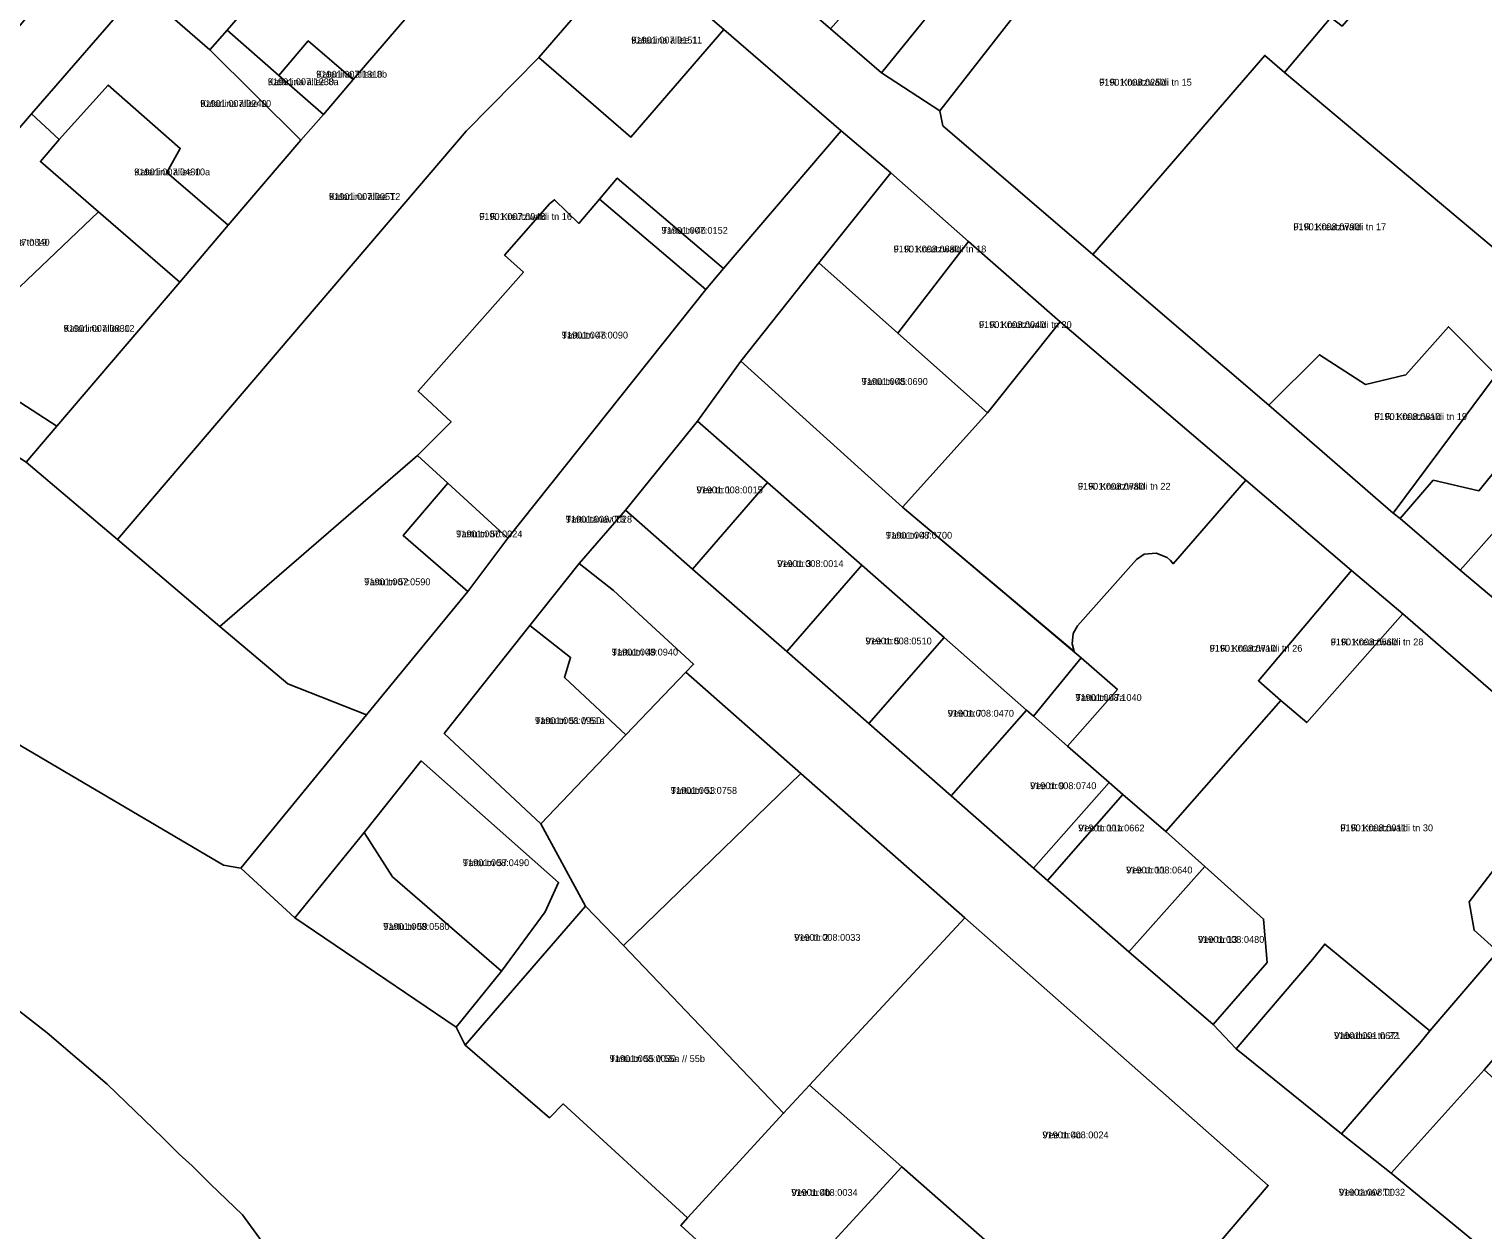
# Model space of a CAD drawing. Extents: x 675810 to 681273, y 6411190 to 6417565.
# Drawn here: x 677508.4 to 677826.5, y 6415288.2 to 6415551.1 of the extents above; entities that cross this region are included whole.
import ezdxf

# ---------------------------------------------------------------- set-up
doc = ezdxf.new("R2010")
doc.units = 0
for name, color, linetype in [('L_AADRESS', 7, 'Continuous'), ('PIIR', 7, 'Continuous'), ('TUNNUS', 7, 'Continuous')]:
    doc.layers.add(name, color=color, linetype=linetype)

msp = doc.modelspace()

# ---------------------------------------------------------------- linework, layer by layer
at = {"layer": 'PIIR'}
for points in [[(677842.69, 6415606.39), (677795.01, 6415644.29), (677786.34, 6415633.16), (677765.5, 6415606.74), (677740.8, 6415575.7), (677707.68, 6415533.22), (677694.9, 6415541.55), (677704.67, 6415553.58), (677711.53, 6415562.1), (677736.52, 6415593.55), (677779.85, 6415648.18), (677801.3, 6415675.96), (677820.17, 6415699.87), (677831.96, 6415720.82)], [(677495.67, 6415713.67), (677508.64, 6415702.82), (677531.61, 6415681.39), (677532.23, 6415682.05), (677579.84, 6415640.53), (677582.81, 6415640.69), (677592.98, 6415629.43), (677599.34, 6415623.94), (677607.64, 6415617.12), (677629.42, 6415597.96), (677651.47, 6415579), (677664.86, 6415567.49), (677683.76, 6415551.18), (677694.9, 6415541.55), (677707.68, 6415533.22), (677708.33, 6415529.95), (677741.16, 6415501.73), (677779.68, 6415468.8), (677806.89, 6415445.16), (677808.38, 6415444), (677821.56, 6415432.66), (677839.41, 6415417.62)], [(677841.37, 6415395.02), (677809, 6415423.1), (677797.76, 6415432.58), (677774.64, 6415452.34), (677734.01, 6415487.03), (677713.91, 6415504.57), (677696.92, 6415519.61), (677686.05, 6415528.82), (677660.36, 6415551.02), (677640.22, 6415568.39), (677619.3, 6415586.7), (677597.33, 6415605.55), (677583.03, 6415617.83), (677571.56, 6415627.5), (677552.93, 6415643.54), (677533.97, 6415659.49), (677514.58, 6415676.17), (677498.11, 6415690.24)], [(677747.14, 6415260.04), (677779.53, 6415298.01), (677713.15, 6415356.53), (677677.25, 6415388.18), (677652.1, 6415410.33), (677653.79, 6415412.07), (677636.22, 6415428.22), (677628.7, 6415434.13), (677638.86, 6415445.76), (677653.53, 6415432.91), (677674.17, 6415414.84), (677692.1, 6415399.1), (677710.14, 6415383.26), (677728.17, 6415367.42), (677731.22, 6415364.74), (677749.05, 6415349.09), (677767.49, 6415333.18), (677772.54, 6415327.91), (677795.57, 6415309.3), (677806.4, 6415300.64), (677832.58, 6415279.14)], [(677485.36, 6415406.68), (677550.88, 6415368.11), (677554.69, 6415367.45), (677566.49, 6415356.58), (677601.8, 6415332.63), (677603.77, 6415328.68), (677622.25, 6415312.81), (677625.2, 6415315.85), (677652.45, 6415290.88), (677650.98, 6415289.25), (677670.83, 6415271.06), (677666.68, 6415266.54), (677648.5, 6415245.63), (677700.59, 6415199.01), (677718.76, 6415219.92), (677731.04, 6415208.96), (677712.89, 6415188.04), (677750.89, 6415154.12), (677743.82, 6415145.67), (677809.68, 6415088.2), (677848.98, 6415054.08)], [(677495.96, 6415344.11), (677512.33, 6415331.37), (677525.47, 6415320.12), (677537.61, 6415308.38), (677541.2, 6415304.85), (677544.01, 6415302.26), (677548.03, 6415298.26), (677555.03, 6415291.57), (677559.39, 6415285.68)], [(677559.39, 6415285.68), (677555.03, 6415291.57), (677548.03, 6415298.26), (677544.01, 6415302.26), (677541.2, 6415304.85), (677537.61, 6415308.38), (677525.47, 6415320.12), (677512.33, 6415331.37), (677495.96, 6415344.11)]]:
    msp.add_lwpolyline(points, dxfattribs=at)
for points in [[(677571.56, 6415627.5), (677583.03, 6415617.83), (677551.18, 6415581.36), (677549.66, 6415579.59), (677532.56, 6415559.91), (677508.91, 6415532.58), (677473.16, 6415490.87), (677460.53, 6415498.36), (677472.49, 6415512.66), (677485.32, 6415527.43), (677497.44, 6415541.36), (677520.31, 6415568.6), (677535.54, 6415586.39), (677546.64, 6415598.81)], [(677939.15, 6415495.17), (677942.44, 6415488.99), (677885.15, 6415422.56), (677876.27, 6415430.13), (677861.05, 6415443.12), (677844.04, 6415458.03), (677841.47, 6415460.28), (677849.59, 6415469.04), (677858, 6415478.15), (677841.91, 6415492.28), (677783.11, 6415541.62), (677793.25, 6415553.63), (677795.68, 6415551.77), (677812.82, 6415571.64), (677842.69, 6415606.39), (677844.64, 6415608.67), (677849.65, 6415604.71), (677905.42, 6415560.52), (677907.63, 6415562.8), (677911.67, 6415559.3), (677933.66, 6415540.22), (677949.24, 6415526.71), (677959.46, 6415517.95)], [(677619.3, 6415586.7), (677640.22, 6415568.39), (677619.9, 6415544.86), (677604, 6415528.75), (677527.68, 6415439.36), (677507.74, 6415456.28), (677514.44, 6415464.15), (677541.32, 6415495.69), (677551.91, 6415508.21), (677567.84, 6415526.77), (677572.82, 6415532.42), (677579.26, 6415540.06), (677605.9, 6415571.07)], [(677565.03, 6415566.32), (677551.68, 6415550.86), (677547.88, 6415546.59), (677532.56, 6415559.91), (677549.66, 6415579.59)], [(677551.68, 6415550.86), (677565.03, 6415566.32), (677566.5, 6415568.03), (677565.12, 6415569.23), (677569.8, 6415574.5), (677576.81, 6415568.48), (677597.12, 6415578.84), (677605.9, 6415571.07), (677579.26, 6415540.06), (677569.45, 6415548.5), (677563.01, 6415540.96)], [(677766.43, 6415556.59), (677776.12, 6415566.66), (677793.25, 6415553.63), (677783.11, 6415541.62), (677778.77, 6415545.33), (677741.16, 6415501.73), (677708.33, 6415529.95), (677707.68, 6415533.22), (677740.8, 6415575.7)], [(677619.9, 6415544.86), (677640.22, 6415568.39), (677660.36, 6415551.02), (677640.04, 6415527.46)], [(677690.04, 6415558.3), (677693.92, 6415562.66), (677696.21, 6415560.67), (677704.67, 6415553.58), (677694.9, 6415541.55), (677683.76, 6415551.18)], [(677547.88, 6415546.59), (677567.84, 6415526.77), (677551.91, 6415508.21), (677538.47, 6415519.68), (677541.45, 6415524.99), (677525.69, 6415538.85), (677514.96, 6415526.92), (677508.91, 6415532.58), (677532.56, 6415559.91)], [(677377.21, 6415550.75), (677395.17, 6415538.44), (677460.53, 6415498.36), (677473.16, 6415490.87), (677490.51, 6415479.64), (677514.44, 6415464.15), (677507.74, 6415456.28), (677392.53, 6415530.33), (677391.54, 6415531.46), (677372.02, 6415544.64)], [(677619.9, 6415544.86), (677640.04, 6415527.46), (677660.36, 6415551.02), (677686.05, 6415528.82), (677660.34, 6415498.69), (677637.06, 6415518.47), (677633.17, 6415513.9), (677628.64, 6415508.56), (677623.3, 6415513.75), (677622.3, 6415512.91), (677612.41, 6415501.6), (677616.52, 6415497.9), (677593.48, 6415471.85), (677600.71, 6415465.11), (677593.38, 6415457.73), (677550.13, 6415420.31), (677527.68, 6415439.36), (677604, 6415528.75)], [(677547.88, 6415546.59), (677551.68, 6415550.86), (677563.01, 6415540.96), (677572.82, 6415532.42), (677567.84, 6415526.77)], [(677563.01, 6415540.96), (677569.45, 6415548.5), (677579.26, 6415540.06), (677572.82, 6415532.42)], [(677783.11, 6415541.62), (677841.91, 6415492.28), (677829.39, 6415475.44), (677818.94, 6415485.93), (677809.63, 6415475.43), (677800.8, 6415473.32), (677790.72, 6415479.82), (677779.68, 6415468.8), (677741.16, 6415501.73), (677778.77, 6415545.33)], [(677523.55, 6415511.07), (677510.82, 6415522.1), (677514.96, 6415526.92), (677525.69, 6415538.85), (677541.45, 6415524.99), (677538.47, 6415519.68), (677551.91, 6415508.21), (677541.32, 6415495.69)], [(677473.16, 6415490.87), (677508.91, 6415532.58), (677514.96, 6415526.92), (677510.82, 6415522.1), (677523.55, 6415511.07), (677490.51, 6415479.64)], [(677392.53, 6415530.33), (677507.74, 6415456.28), (677527.68, 6415439.36), (677550.13, 6415420.31), (677564.99, 6415407.75), (677582.2, 6415400.99), (677554.69, 6415367.45), (677550.88, 6415368.11), (677485.36, 6415406.68), (677406.64, 6415436.15), (677370.49, 6415446.92), (677334.72, 6415460.59), (677337.9, 6415464.39), (677355.53, 6415485.48), (677358.99, 6415489.69), (677380.91, 6415516.25)], [(677686.05, 6415528.82), (677696.92, 6415519.61), (677681.17, 6415499.93), (677664.09, 6415478.39), (677654.6, 6415465.28), (677638.86, 6415445.76), (677628.7, 6415434.13), (677617.95, 6415420.52), (677599.21, 6415396.91), (677620.31, 6415377.13), (677630.11, 6415359.11), (677603.77, 6415328.68), (677601.8, 6415332.63), (677611.76, 6415344.87), (677621.32, 6415357.89), (677624.24, 6415364.29), (677594.19, 6415390.9), (677581.67, 6415375.21), (677566.49, 6415356.58), (677554.69, 6415367.45), (677582.2, 6415400.99), (677604.35, 6415428), (677613.09, 6415439.69), (677656.45, 6415494.11), (677660.34, 6415498.69)], [(677637.06, 6415518.47), (677660.34, 6415498.69), (677656.45, 6415494.11), (677633.17, 6415513.9)], [(677698.44, 6415484.56), (677681.17, 6415499.93), (677696.92, 6415519.61), (677713.91, 6415504.57)], [(677656.45, 6415494.11), (677613.09, 6415439.69), (677599.98, 6415451.68), (677593.38, 6415457.73), (677600.71, 6415465.11), (677593.48, 6415471.85), (677616.52, 6415497.9), (677612.41, 6415501.6), (677622.3, 6415512.91), (677623.3, 6415513.75), (677628.64, 6415508.56), (677633.17, 6415513.9)], [(677490.51, 6415479.64), (677523.55, 6415511.07), (677541.32, 6415495.69), (677514.44, 6415464.15)], [(677718.11, 6415467.08), (677698.44, 6415484.56), (677713.91, 6415504.57), (677734.01, 6415487.03)], [(677698.44, 6415484.56), (677718.11, 6415467.08), (677699.47, 6415446.48), (677664.09, 6415478.39), (677681.17, 6415499.93)], [(677849.59, 6415469.04), (677844.71, 6415473.53), (677825.64, 6415450.04), (677815.63, 6415452.36), (677808.38, 6415444), (677806.89, 6415445.16), (677829.39, 6415475.44), (677841.91, 6415492.28), (677858, 6415478.15)], [(677738.59, 6415413.5), (677699.47, 6415446.48), (677718.11, 6415467.08), (677734.01, 6415487.03), (677774.64, 6415452.34), (677758.71, 6415434.08), (677758.17, 6415434.77), (677757.43, 6415435.41), (677754.97, 6415436.35), (677752.37, 6415436.2), (677750.67, 6415435.02), (677737.77, 6415420.49), (677736.81, 6415418.82), (677736.62, 6415416.51), (677737.03, 6415414.83)], [(677806.89, 6415445.16), (677779.68, 6415468.8), (677790.72, 6415479.82), (677800.8, 6415473.32), (677809.63, 6415475.43), (677818.94, 6415485.93), (677829.39, 6415475.44)], [(677690.61, 6415433.79), (677669.96, 6415451.85), (677654.6, 6415465.28), (677664.09, 6415478.39), (677699.47, 6415446.48), (677737.03, 6415414.83), (677738.59, 6415413.5), (677728.15, 6415400.72), (677726.65, 6415402.05), (677708.61, 6415417.89)], [(677849.59, 6415469.04), (677841.47, 6415460.28), (677844.04, 6415458.03), (677838.9, 6415452.24), (677821.56, 6415432.66), (677808.38, 6415444), (677815.63, 6415452.36), (677825.64, 6415450.04), (677844.71, 6415473.53)], [(677638.86, 6415445.76), (677654.6, 6415465.28), (677669.96, 6415451.85), (677653.53, 6415432.91)], [(677564.99, 6415407.75), (677550.13, 6415420.31), (677593.38, 6415457.73), (677599.98, 6415451.68), (677590.25, 6415440.22), (677604.35, 6415428), (677582.2, 6415400.99)], [(677838.9, 6415452.24), (677844.04, 6415458.03), (677861.05, 6415443.12), (677839.41, 6415417.62), (677821.56, 6415432.66)], [(677599.98, 6415451.68), (677613.09, 6415439.69), (677604.35, 6415428), (677590.25, 6415440.22)], [(677653.53, 6415432.91), (677669.96, 6415451.85), (677690.61, 6415433.79), (677674.17, 6415414.84)], [(677746.51, 6415406.54), (677738.59, 6415413.5), (677737.03, 6415414.83), (677736.62, 6415416.51), (677736.81, 6415418.82), (677737.77, 6415420.49), (677750.67, 6415435.02), (677752.37, 6415436.2), (677754.97, 6415436.35), (677757.43, 6415435.41), (677758.17, 6415434.77), (677758.71, 6415434.08), (677774.64, 6415452.34), (677797.76, 6415432.58), (677777.38, 6415408.47), (677782.3, 6415404.17), (677757.14, 6415375.49), (677747.73, 6415383.53), (677744.68, 6415386.21), (677735.63, 6415394.16)], [(677636.22, 6415428.22), (677653.79, 6415412.07), (677652.1, 6415410.33), (677638.92, 6415396.61), (677625.52, 6415409.19), (677626.85, 6415413.56), (677617.95, 6415420.52), (677628.7, 6415434.13)], [(677674.17, 6415414.84), (677690.61, 6415433.79), (677708.61, 6415417.89), (677692.1, 6415399.1)], [(677809, 6415423.1), (677787.95, 6415399.31), (677782.3, 6415404.17), (677777.38, 6415408.47), (677797.76, 6415432.58)], [(677809, 6415423.1), (677841.37, 6415395.02), (677834.02, 6415386.52), (677833.31, 6415372.88), (677823.52, 6415360.05), (677824.57, 6415353.84), (677829.76, 6415349.23), (677814.91, 6415331.84), (677791.89, 6415350.81), (677789.19, 6415347.45), (677772.54, 6415327.91), (677767.49, 6415333.18), (677779.28, 6415346.77), (677778.51, 6415356.3), (677765.65, 6415367.78), (677757.14, 6415375.49), (677782.3, 6415404.17), (677787.95, 6415399.31)], [(677626.85, 6415413.56), (677625.52, 6415409.19), (677638.92, 6415396.61), (677620.31, 6415377.13), (677599.21, 6415396.91), (677617.95, 6415420.52)], [(677726.65, 6415402.05), (677710.14, 6415383.26), (677692.1, 6415399.1), (677708.61, 6415417.89)], [(677728.15, 6415400.72), (677738.59, 6415413.5), (677746.51, 6415406.54), (677735.63, 6415394.16)], [(677630.11, 6415359.11), (677620.31, 6415377.13), (677638.92, 6415396.61), (677652.1, 6415410.33), (677677.25, 6415388.18), (677638.44, 6415350.49)], [(677710.14, 6415383.26), (677726.65, 6415402.05), (677728.15, 6415400.72), (677735.63, 6415394.16), (677744.68, 6415386.21), (677728.17, 6415367.42)], [(677841.37, 6415395.02), (677857.43, 6415381.2), (677829.76, 6415349.23), (677824.57, 6415353.84), (677823.52, 6415360.05), (677833.31, 6415372.88), (677834.02, 6415386.52)], [(677581.67, 6415375.21), (677594.19, 6415390.9), (677624.24, 6415364.29), (677621.32, 6415357.89), (677611.76, 6415344.87), (677587.88, 6415365.55)], [(677677.25, 6415388.18), (677713.15, 6415356.53), (677679.14, 6415319.9), (677673.45, 6415313.78), (677638.44, 6415350.49)], [(677747.73, 6415383.53), (677731.22, 6415364.74), (677728.17, 6415367.42), (677744.68, 6415386.21)], [(677731.22, 6415364.74), (677747.73, 6415383.53), (677757.14, 6415375.49), (677765.65, 6415367.78), (677749.05, 6415349.09)], [(677857.43, 6415381.2), (677868.64, 6415371.47), (677854.25, 6415354.9), (677841, 6415339.65), (677826.76, 6415323.27), (677806.4, 6415300.64), (677795.57, 6415309.3), (677812.73, 6415329.11), (677814.91, 6415331.84), (677829.76, 6415349.23)], [(677566.49, 6415356.58), (677581.67, 6415375.21), (677587.88, 6415365.55), (677611.76, 6415344.87), (677601.8, 6415332.63)], [(677749.05, 6415349.09), (677765.65, 6415367.78), (677778.51, 6415356.3), (677779.28, 6415346.77), (677767.49, 6415333.18)], [(677622.25, 6415312.81), (677603.77, 6415328.68), (677630.11, 6415359.11), (677638.44, 6415350.49), (677673.45, 6415313.78), (677652.45, 6415290.88), (677625.2, 6415315.85)], [(677713.15, 6415356.53), (677779.53, 6415298.01), (677747.14, 6415260.04), (677699.36, 6415302.08), (677679.14, 6415319.9)], [(677789.19, 6415347.45), (677791.89, 6415350.81), (677814.91, 6415331.84), (677812.73, 6415329.11), (677795.57, 6415309.3), (677772.54, 6415327.91)], [(677826.76, 6415323.27), (677851.33, 6415301.12), (677832.58, 6415279.14), (677806.4, 6415300.64)], [(677679.14, 6415319.9), (677699.36, 6415302.08), (677673.87, 6415274.36), (677670.83, 6415271.06), (677650.98, 6415289.25), (677652.45, 6415290.88), (677673.45, 6415313.78)], [(677699.36, 6415302.08), (677747.14, 6415260.04), (677722.98, 6415231.8), (677673.87, 6415274.36)]]:
    msp.add_lwpolyline(points, close=True, dxfattribs=at)

# ---------------------------------------------------------------- texts
at = {"layer": 'L_AADRESS'}
for s, p in [('Katariina allee 11', (677640.13, 6415547.93)), ('Katariina allee 8a', (677560.59, 6415538.82)), ('Katariina allee 8b', (677571.19, 6415540.46)), ('F. R. Kreutzwaldi tn 15', (677742.51, 6415538.71)), ('Katariina allee 10', (677545.82, 6415534.06)), ('Katariina allee 10a', (677531.36, 6415519.08)), ('Katariina allee T2', (677573.98, 6415513.69)), ('F. R. Kreutzwaldi tn 16', (677606.86, 6415509.32)), ('F. R. Kreutzwaldi tn 17', (677785.03, 6415507.07)), ('L. Koidula tn 19', (677498.35, 6415503.68)), ('Tartu tn 46', (677646.76, 6415506.29)), ('F. R. Kreutzwaldi tn 18', (677697.54, 6415502.21)), ('Katariina allee 12', (677515.91, 6415484.84)), ('F. R. Kreutzwaldi tn 20', (677716.22, 6415485.65)), ('Tartu tn 48', (677624.92, 6415483.36)), ('Tartu tn 45', (677690.53, 6415473.21)), ('F. R. Kreutzwaldi tn 19', (677802.73, 6415465.54)), ('Vee tn 1', (677654.41, 6415449.48)), ('F. R. Kreutzwaldi tn 22', (677737.86, 6415450.27)), ('Tartu tänav T3', (677625.8, 6415443.06)), ('Tartu tn 50', (677601.81, 6415439.84)), ('Tartu tn 47', (677695.85, 6415439.55)), ('Vee tn 3', (677672.07, 6415433.35)), ('Tartu tn 52', (677581.69, 6415429.36)), ('Vee tn 5', (677691.39, 6415416.41)), ('F. R. Kreutzwaldi tn 26', (677766.7, 6415414.81)), ('F. R. Kreutzwaldi tn 28', (677793.19, 6415416.2)), ('Tartu tn 49', (677635.87, 6415413.98)), ('Tartu tn 47a', (677737.33, 6415404.03)), ('Tartu tn 51 // 51a', (677619.07, 6415398.97)), ('Vee tn 7', (677709.38, 6415400.58)), ('Tartu tn 53', (677648.78, 6415383.7)), ('Vee tn 9', (677727.41, 6415384.73)), ('Vee tn 11a', (677737.95, 6415375.48)), ('F. R. Kreutzwaldi tn 30', (677795.3, 6415375.51)), ('Tartu tn 57', (677603.28, 6415367.88)), ('Vee tn 11', (677748.43, 6415366.28)), ('Tartu tn 59', (677585.86, 6415353.92)), ('Vee tn 2', (677675.79, 6415351.53)), ('Vee tn 13', (677764.16, 6415351.08)), ('Vabaduse tn 22', (677793.93, 6415330.05)), ('Tartu tn 55 // 55a // 55b', (677635.41, 6415324.99)), ('Vee tn 4c', (677730.1, 6415308.29)), ('Vee tn 4b', (677675.17, 6415295.7)), ('Vee tänav T1', (677794.98, 6415295.75))]:
    msp.add_text(s, height=1.5, dxfattribs=at).set_placement(p)
at = {"layer": 'TUNNUS'}
for s, p in [('91901:007:0151', (677640.13, 6415547.93)), ('91901:007:1230', (677560.59, 6415538.82)), ('91901:007:1310', (677571.19, 6415540.46)), ('91901:008:0250', (677742.51, 6415538.71)), ('91901:007:0240', (677545.82, 6415534.06)), ('91901:007:0430', (677531.36, 6415519.08)), ('91901:007:0051', (677573.98, 6415513.69)), ('91901:007:0048', (677606.86, 6415509.32)), ('91901:008:0790', (677785.03, 6415507.07)), ('91901:007:0840', (677498.35, 6415503.68)), ('91901:007:0152', (677646.76, 6415506.29)), ('91901:008:0880', (677697.54, 6415502.21)), ('91901:007:0830', (677515.91, 6415484.84)), ('91901:008:0040', (677716.22, 6415485.65)), ('91901:007:0090', (677624.92, 6415483.36)), ('91901:008:0690', (677690.53, 6415473.21)), ('91901:008:0810', (677802.73, 6415465.54)), ('91901:008:0015', (677654.41, 6415449.48)), ('91901:008:0780', (677737.86, 6415450.27)), ('91901:008:0028', (677625.8, 6415443.06)), ('91901:007:0024', (677601.81, 6415439.84)), ('91901:008:0700', (677695.85, 6415439.55)), ('91901:008:0014', (677672.07, 6415433.35)), ('91901:007:0590', (677581.69, 6415429.36)), ('91901:008:0510', (677691.39, 6415416.41)), ('91901:008:0710', (677766.7, 6415414.81)), ('91901:008:0560', (677793.19, 6415416.2)), ('91901:008:0940', (677635.87, 6415413.98)), ('91901:008:1040', (677737.33, 6415404.03)), ('91901:008:0950', (677619.07, 6415398.97)), ('91901:008:0470', (677709.38, 6415400.58)), ('91901:001:0758', (677648.78, 6415383.7)), ('91901:008:0740', (677727.41, 6415384.73)), ('91901:001:0662', (677737.95, 6415375.48)), ('91901:008:0011', (677795.3, 6415375.51)), ('91901:008:0490', (677603.28, 6415367.88)), ('91901:008:0640', (677748.43, 6415366.28)), ('91901:008:0580', (677585.86, 6415353.92)), ('91901:008:0033', (677675.79, 6415351.53)), ('91901:008:0480', (677764.16, 6415351.08)), ('91901:001:0671', (677793.93, 6415330.05)), ('91901:008:0030', (677635.41, 6415324.99)), ('91901:008:0024', (677730.1, 6415308.29)), ('91901:008:0034', (677675.17, 6415295.7)), ('91901:008:0032', (677794.98, 6415295.75))]:
    msp.add_text(s, height=1.5, dxfattribs=at).set_placement(p)

doc.saveas('drawing.dxf')
